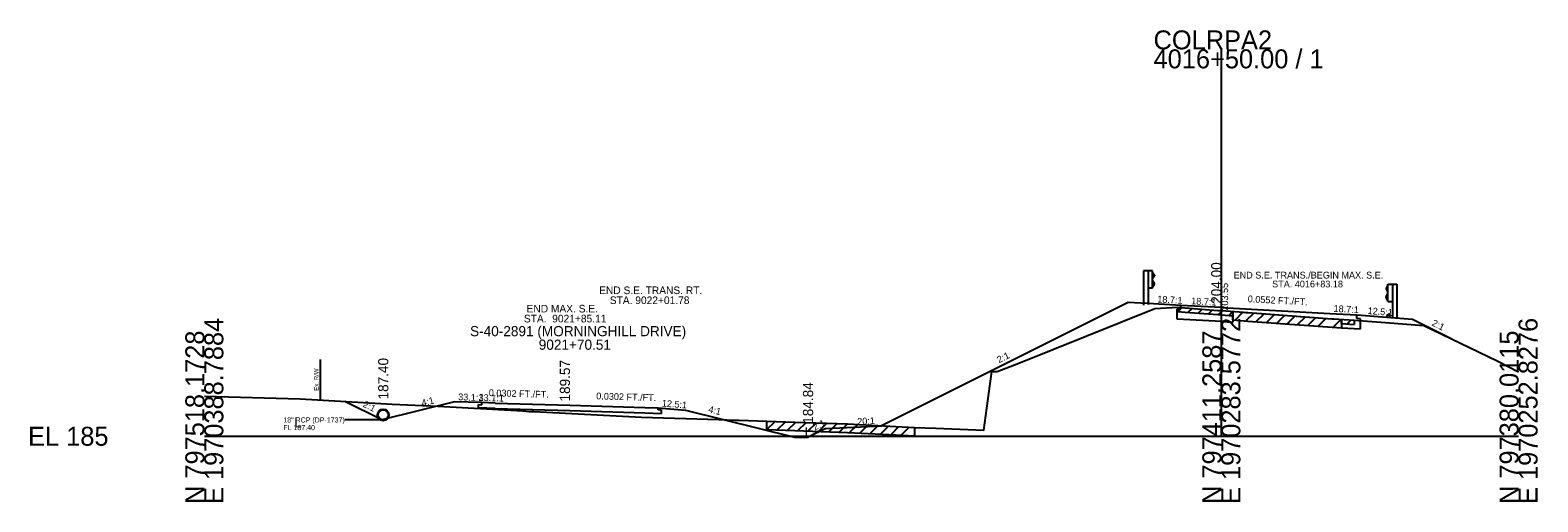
# Model space of a CAD drawing. Extents: x -26 to 1971083, y -10 to 798159.
# Drawn here: x -25.7 to 196.7, y 990.3 to 1060 of the extents above; entities that cross this region are included whole.
import ezdxf

# ---------------------------------------------------------------- set-up
doc = ezdxf.new("R2010")
doc.units = 0
for name, color, linetype in [('RD_GPK_XS_Cell', 7, 'Continuous'), ('RD_XS_Base', 7, 'Continuous'), ('RD_XS_CurbTop', 7, 'Continuous'), ('RD_XS_EarthShd', 7, 'Continuous'), ('RD_XS_ExGround', 7, 'Continuous'), ('RD_XS_ExPaveRet', 7, 'Continuous'), ('RD_XS_ExRW', 7, 'Continuous'), ('RD_XS_GR', 7, 'Continuous'), ('RD_XS_Misc_Line', 7, 'Continuous'), ('RD_XS_Pave', 7, 'Continuous'), ('RD_XS_PaveOvlay', 7, 'Continuous'), ('RD_XS_PaveShd', 7, 'Continuous'), ('RD_XS_Pipe', 7, 'Continuous'), ('RD_XS_TieSlope', 7, 'Continuous'), ('RD_XS_TX_Elev_EX', 7, 'Continuous'), ('RD_XS_TX_Elev_PR', 7, 'Continuous'), ('RD_XS_TX_Misc', 7, 'Continuous'), ('RD_XS_TX_MkPT', 7, 'Continuous'), ('RD_XS_TX_Notes', 7, 'Continuous'), ('RD_XS_TX_Profile', 7, 'Continuous'), ('RD_XS_TX_ShdSlope', 7, 'Continuous'), ('RD_XS_TX_Slope', 7, 'Continuous'), ('RD_XS_TX_Station', 7, 'Continuous')]:
    doc.layers.add(name, color=color, linetype=linetype)

msp = doc.modelspace()

# ---------------------------------------------------------------- linework, layer by layer
at = {"layer": 'RD_GPK_XS_Cell'}
for p, q in [((150, 1000), (150, 1057.13)), ((0, 1000), (150, 1000)), ((150, 1000), (193.84, 1000))]:
    msp.add_line(p, q, dxfattribs=at)
at = {"layer": 'RD_XS_Base'}
for p, q in [((143.5, 1018.79), (144, 1018.77)), ((143.5, 1017.31), (143.5, 1018.79)), ((144, 1018.77), (144, 1019.33)), ((150, 1016.96), (143.5, 1017.31)), ((150, 1016.96), (151.7, 1016.87)), ((170, 1017.37), (170, 1017.93)), ((170.5, 1017.35), (170, 1017.37)), ((170.5, 1015.87), (170.5, 1017.35)), ((167.72, 1016.01), (170.5, 1015.87)), ((40.41, 1004.68), (40.91, 1004.66)), ((40.41, 1004.2), (40.41, 1004.68)), ((42.91, 1004.12), (40.41, 1004.2)), ((40.91, 1004.66), (40.91, 1004.96)), ((42.91, 1004.12), (53.93, 1003.79)), ((53.93, 1003.79), (64.95, 1003.46)), ((64.95, 1003.46), (67.45, 1003.38)), ((66.95, 1003.88), (66.95, 1004.18)), ((67.45, 1003.86), (66.95, 1003.88)), ((67.45, 1003.38), (67.45, 1003.86))]:
    msp.add_line(p, q, dxfattribs=at)
at = {"layer": 'RD_XS_CurbTop'}
for p, q in [((174.42, 1017.58), (174.66, 1018.03)), ((174.42, 1017.58), (174.88, 1017.54)), ((174.88, 1017.54), (174.82, 1017.98))]:
    msp.add_line(p, q, dxfattribs=at)
msp.add_ellipse((174.74, 1017.95), major_axis=(0, -0.131), ratio=0.686, start_param=1.762783, end_param=4.036677, dxfattribs=at)
at = {"layer": 'RD_XS_EarthShd'}
for p, q in [((144, 1019.33), (140, 1019.54)), ((170, 1017.93), (174.42, 1017.58)), ((40.91, 1004.96), (36.9, 1005.08)), ((66.95, 1004.18), (70.96, 1003.86))]:
    msp.add_line(p, q, dxfattribs=at)
at = {"layer": 'RD_XS_ExGround'}
msp.add_lwpolyline([(0, 1005.92), (14.12, 1005.52), (20.06, 1005.16), (27.68, 1004.74), (34.46, 1004.42), (46.96, 1003.74), (47.85, 1003.67), (48.62, 1003.64), (64.47, 1002.84), (75.9, 1002.46), (78.22, 1002.39), (78.87, 1002.37), (82.97, 1002.24), (87.11, 1002.1), (94.88, 1001.81), (101.98, 1001.45), (104.73, 1001.31), (107.91, 1001.18), (114.97, 1000.88), (116.14, 1009.56), (116.94, 1009.58), (120.12, 1010.77), (140.18, 1018.86), (143.59, 1019.04), (144.64, 1018.96), (149.49, 1018.59), (150, 1018.55), (153.92, 1018.26), (166.27, 1017.36), (166.59, 1017.34), (169.57, 1017.14), (174.2, 1016.79), (179.85, 1016.37), (190.68, 1011.13), (193.84, 1009.51)], dxfattribs=at)
at = {"layer": 'RD_XS_ExPaveRet'}
for p, q in [((143.59, 1018.42), (143.59, 1019.04)), ((143.59, 1018.42), (144.64, 1018.34)), ((144.64, 1018.34), (149.49, 1017.97)), ((149.49, 1017.97), (150, 1017.93)), ((150, 1017.93), (151.7, 1017.8)), ((151.7, 1017.18), (151.7, 1018.43)), ((151.7, 1018.43), (151.7, 1017.8)), ((151.7, 1017.18), (153.92, 1017.01)), ((153.92, 1017.01), (167.72, 1016.01)), ((167.72, 1017.26), (167.72, 1016.01)), ((167.72, 1016.64), (167.72, 1017.26)), ((167.72, 1016.64), (169.57, 1016.51)), ((169.57, 1017.14), (169.57, 1016.51)), ((82.97, 1000.99), (82.97, 1002.24)), ((82.97, 1000.99), (87.11, 1000.85)), ((87.11, 1000.85), (94.88, 1000.56)), ((104.73, 1001.31), (104.73, 1000.06)), ((94.88, 1000.56), (101.98, 1000.2)), ((101.98, 1000.2), (104.73, 1000.06))]:
    msp.add_line(p, q, dxfattribs=at)
at = {"layer": 'RD_XS_ExRW'}
msp.add_line((17.09, 1011.34), (17.09, 1005.34), dxfattribs=at)
at = {"layer": 'RD_XS_GR'}
for p, q in [((139.19, 1024.41), (138.52, 1024.41)), ((138.52, 1024.41), (138.52, 1019.36)), ((139.85, 1024.41), (139.19, 1024.41)), ((139.19, 1024.41), (139.19, 1019.47)), ((139.85, 1021.85), (139.85, 1024.41)), ((139.85, 1024.25), (140.12, 1023.81)), ((140.12, 1023.7), (139.85, 1023.26)), ((140.12, 1022.56), (139.85, 1023)), ((140.12, 1023.81), (140.12, 1023.7)), ((139.85, 1021.85), (139.19, 1021.85)), ((139.85, 1022.01), (140.12, 1022.45)), ((140.12, 1022.45), (140.12, 1022.56)), ((174.56, 1022.29), (174.29, 1021.85)), ((174.29, 1021.85), (174.29, 1021.74)), ((174.29, 1021.74), (174.56, 1021.3)), ((174.29, 1020.6), (174.56, 1021.04)), ((174.56, 1022.45), (175.23, 1022.45)), ((174.56, 1019.88), (174.56, 1022.45)), ((175.23, 1022.45), (175.89, 1022.45)), ((175.23, 1022.45), (175.23, 1017.51)), ((175.89, 1022.45), (175.89, 1017.4)), ((174.29, 1020.49), (174.29, 1020.6)), ((174.56, 1020.05), (174.29, 1020.49)), ((174.56, 1019.88), (175.23, 1019.88))]:
    msp.add_line(p, q, dxfattribs=at)
at = {"layer": 'RD_XS_Misc_Line'}
for p, q in [((143.59, 1018.42), (144.17, 1019)), ((145.1, 1018.3), (145.68, 1018.88)), ((146.6, 1018.19), (147.18, 1018.77)), ((148.1, 1018.07), (148.68, 1018.65)), ((149.6, 1017.96), (150.18, 1018.54)), ((151.1, 1017.85), (151.68, 1018.43)), ((152.02, 1017.15), (153.18, 1018.32)), ((153.6, 1017.04), (154.78, 1018.2)), ((155.13, 1016.93), (156.31, 1018.09)), ((156.65, 1016.82), (157.83, 1017.98)), ((158.17, 1016.7), (159.35, 1017.87)), ((159.69, 1016.59), (160.87, 1017.76)), ((161.22, 1016.48), (162.4, 1017.64)), ((162.74, 1016.37), (163.92, 1017.53)), ((164.26, 1016.26), (165.44, 1017.42)), ((166.48, 1016.1), (167.65, 1017.27)), ((168.56, 1016.58), (169.15, 1017.17)), ((82.97, 1000.99), (84.2, 1002.2)), ((84.49, 1000.94), (85.72, 1002.15)), ((86.02, 1000.89), (87.24, 1002.1)), ((87.54, 1000.83), (88.76, 1002.04)), ((89.06, 1000.78), (90.28, 1001.98)), ((90.58, 1000.72), (91.81, 1001.92)), ((92.11, 1000.66), (93.33, 1001.87)), ((93.63, 1000.61), (94.85, 1001.81)), ((95.15, 1000.54), (96.36, 1001.73)), ((96.68, 1000.47), (97.88, 1001.66)), ((98.2, 1000.39), (99.4, 1001.58)), ((99.72, 1000.31), (100.93, 1001.5)), ((101.24, 1000.23), (102.45, 1001.42)), ((102.77, 1000.16), (103.97, 1001.35))]:
    msp.add_line(p, q, dxfattribs=at)
at = {"layer": 'RD_XS_Pave'}
for p, q in [((150, 1019), (166, 1018.15)), ((42.91, 1004.9), (53.93, 1004.57)), ((53.93, 1004.57), (64.95, 1004.24))]:
    msp.add_line(p, q, dxfattribs=at)
at = {"layer": 'RD_XS_PaveOvlay'}
for p, q in [((151.7, 1018.43), (151.7, 1016.87)), ((153.6, 1018.29), (153.92, 1018.26)), ((153.92, 1018.26), (165.56, 1017.41)), ((167.72, 1017.26), (167.72, 1016.01))]:
    msp.add_line(p, q, dxfattribs=at)
at = {"layer": 'RD_XS_PaveShd'}
for p, q in [((150, 1019), (144, 1019.33)), ((166, 1018.15), (170, 1017.93)), ((42.91, 1004.9), (40.91, 1004.96)), ((64.95, 1004.24), (66.95, 1004.18))]:
    msp.add_line(p, q, dxfattribs=at)
at = {"layer": 'RD_XS_Pipe'}
for p, q in [((25.7, 1002.4), (20.7, 1002.4)), ((25.87, 1002.4), (20.87, 1002.4))]:
    msp.add_line(p, q, dxfattribs=at)
for radius in [0.85, 0.75]:
    msp.add_circle((26.37, 1003.15), radius, dxfattribs=at)
at = {"layer": 'RD_XS_TieSlope'}
for p, q in [((136.25, 1019.74), (99.87, 1001.55)), ((140, 1019.54), (136.25, 1019.74)), ((174.42, 1017.58), (178.17, 1017.28)), ((178.17, 1017.28), (183.99, 1014.37)), ((26.16, 1002.4), (20.71, 1005.13)), ((36.9, 1005.08), (26.16, 1002.4)), ((70.96, 1003.86), (87.04, 999.84)), ((91.65, 1001.14), (89.04, 999.84)), ((91.65, 1001.14), (99.88, 1001.55)), ((87.04, 999.84), (89.09, 999.84))]:
    msp.add_line(p, q, dxfattribs=at)

# ---------------------------------------------------------------- texts
at = {"layer": 'RD_GPK_XS_Cell'}
for s, p in [('COLRPA2', (140, 1057.13)), ('4016+50.00 / 1', (140, 1054.33)), ('EL 185', (-26, 998.6))]:
    msp.add_text(s, height=2.8, dxfattribs=at).set_placement(p)
for s, p in [('E 1970388.7884', (2.8, 990)), ('E 1970283.5772', (152.8, 990)), ('E 1970252.8276', (196.64, 990)), ('N 797518.1728', (0, 990)), ('N 797411.2587', (150, 990)), ('N 797380.0115', (193.84, 990))]:
    msp.add_text(s, height=2.8, rotation=90, dxfattribs=at).set_placement(p)
at = {"layer": 'RD_XS_ExRW'}
msp.add_text('Ex. R/W ', height=0.65, rotation=90, dxfattribs=at).set_placement((16.84, 1006.72))
at = {"layer": 'RD_XS_Pipe'}
for s, p in [('18" RCP (DP-1737)', (11.65, 1002.03)), ('FL 187.40', (11.65, 1000.9))]:
    msp.add_text(s, height=0.75, dxfattribs=at).set_placement(p)
at = {"layer": 'RD_XS_TX_Elev_EX'}
msp.add_text('203.55', height=1, rotation=90, dxfattribs=at).set_placement((151, 1018.55))
at = {"layer": 'RD_XS_TX_Elev_PR'}
for s, p in [(' 204.00', (150, 1019)), (' 189.57', (53.93, 1004.57))]:
    msp.add_text(s, height=1.5, rotation=90, dxfattribs=at).set_placement(p)
at = {"layer": 'RD_XS_TX_Misc'}
for s, p in [('187.40', (27.14, 1005.43)), ('184.84', (89.79, 1001.84))]:
    msp.add_text(s, height=1.5, rotation=90, dxfattribs=at).set_placement(p)
at = {"layer": 'RD_XS_TX_MkPT'}
for p in [(13.25, 1001.3), (88.53, 999.84)]:
    msp.add_text('L', height=1.5, dxfattribs=at).set_placement(p)
at = {"layer": 'RD_XS_TX_Notes'}
for s, height, p in [('END S.E. TRANS./BEGIN MAX. S.E. ', 1, (151.81, 1023.29)), ('STA. 4016+83.18', 1, (157.49, 1021.98)), ('END S.E. TRANS. RT. ', 1.125, (58.23, 1020.99)), ('END MAX. S.E.', 1.125, (47.52, 1018.28)), ('STA. 9022+01.78', 1.125, (59.8, 1019.52)), ('STA.  9021+85.11', 1.125, (47.13, 1016.81))]:
    msp.add_text(s, height=height, dxfattribs=at).set_placement(p)
at = {"layer": 'RD_XS_TX_Profile'}
msp.add_text('33.1:1', height=1, rotation=358.2681, dxfattribs=at).set_placement((40.44, 1005.23))
at = {"layer": 'RD_XS_TX_ShdSlope'}
for s, rotation, p in [('18.7:1', 356.9323, (140.53, 1019.76)), ('12.5:1', 355.4261, (171.54, 1018.06)), ('33.1:1', 358.2681, (37.43, 1005.32)), ('12.5:1', 355.4323, (67.45, 1004.39))]:
    msp.add_text(s, height=1, rotation=rotation, dxfattribs=at).set_placement(p)
at = {"layer": 'RD_XS_TX_Slope'}
for s, rotation, p in [('0.0552 FT./FT.', 356.9323, (153.87, 1019.8)), ('18.7:1', 356.9323, (145.53, 1019.49)), ('18.7:1', 356.9323, (166.53, 1018.37)), ('2:1', 333.4349, (180.93, 1016.39)), ('2:1', 26.5651, (117.21, 1010.78)), ('2:1', 333.435, (23.28, 1004.4)), ('4:1', 14.0362, (32.16, 1004.41)), ('0.0302 FT./FT.', 358.2681, (41.94, 1005.93)), ('0.0302 FT./FT.', 358.2678, (57.79, 1005.45)), ('4:1', 345.971, (74.26, 1003.55)), ('2:1', 26.5651, (90.03, 1000.82)), ('20:1', 2.8624, (96.32, 1001.68))]:
    msp.add_text(s, height=1, rotation=rotation, dxfattribs=at).set_placement(p)
at = {"layer": 'RD_XS_TX_Station'}
for s, p in [('S-40-2891 (MORNINGHILL DRIVE)', (39.19, 1014.77)), ('9021+70.51', (49.32, 1012.77))]:
    msp.add_text(s, height=1.5, dxfattribs=at).set_placement(p)

doc.saveas('drawing.dxf')
